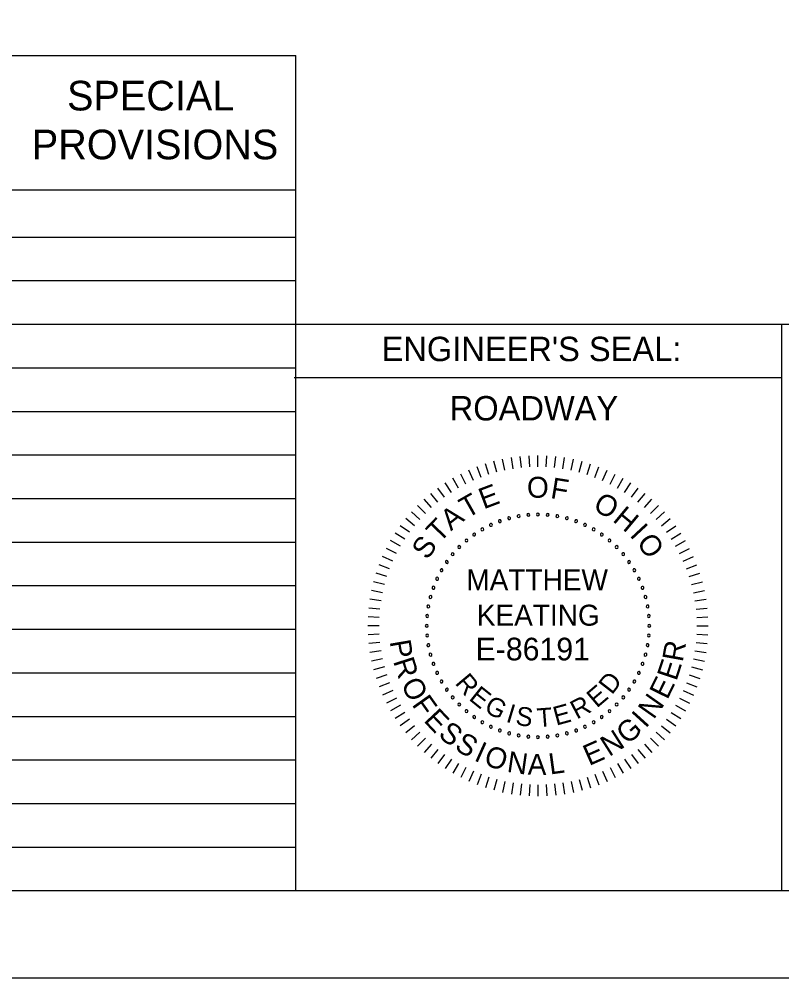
# Model space of a CAD drawing. Extents: x -13.1 to 43.1, y 0 to 22.
# Drawn here: x 23.44 to 27.81, y 0 to 5.5 of the extents above; entities that cross this region are included whole.
import ezdxf

# ---------------------------------------------------------------- set-up
doc = ezdxf.new("R2010")
doc.units = 0
for name, color, linetype in [('SEAL', 7, 'Continuous'), ('SH_Border', 7, 'Continuous'), ('SH_Data', 7, 'Continuous'), ('SH_Text', 7, 'Continuous')]:
    doc.layers.add(name, color=color, linetype=linetype)

msp = doc.modelspace()

# ---------------------------------------------------------------- linework, layer by layer
at = {"layer": 'SEAL'}
for p, q in [((26.2251, 2.9121), (26.2117, 2.9754)), ((26.2721, 2.9208), (26.262, 2.9847)), ((26.3195, 2.927), (26.3127, 2.9914)), ((26.3671, 2.9308), (26.3637, 2.9954)), ((26.4148, 2.932), (26.4148, 2.9967)), ((26.4626, 2.9308), (26.466, 2.9954)), ((26.5102, 2.927), (26.517, 2.9914)), ((26.5576, 2.9208), (26.5677, 2.9847)), ((26.6045, 2.9121), (26.618, 2.9754)), ((26.0878, 2.8714), (26.0647, 2.9318)), ((26.1329, 2.8874), (26.1129, 2.9489)), ((26.1787, 2.9009), (26.1619, 2.9634)), ((26.651, 2.9009), (26.6677, 2.9634)), ((26.6968, 2.8874), (26.7168, 2.9489)), ((26.7418, 2.8714), (26.765, 2.9318)), ((25.9586, 2.8098), (25.9263, 2.8658)), ((26.0006, 2.8326), (25.9712, 2.8902)), ((26.0437, 2.8531), (26.0174, 2.9123)), ((26.786, 2.8531), (26.8123, 2.9123)), ((26.8291, 2.8326), (26.8584, 2.8902)), ((26.8711, 2.8098), (26.9034, 2.8658)), ((25.8785, 2.7578), (25.8405, 2.8101)), ((25.9179, 2.7848), (25.8826, 2.8391)), ((26.9118, 2.7848), (26.947, 2.8391)), ((26.9512, 2.7578), (26.9892, 2.8101)), ((25.8406, 2.7287), (25.7999, 2.779)), ((26.989, 2.7287), (27.0298, 2.779)), ((25.7696, 2.6648), (25.7239, 2.7105)), ((25.8043, 2.6977), (25.761, 2.7458)), ((27.0254, 2.6977), (27.0687, 2.7458)), ((27.06, 2.6648), (27.1058, 2.7105)), ((25.7368, 2.6301), (25.6887, 2.6734)), ((27.0929, 2.6301), (27.141, 2.6734)), ((25.6767, 2.5559), (25.6243, 2.5939)), ((25.7057, 2.5938), (25.6554, 2.6345)), ((27.1239, 2.5938), (27.1742, 2.6345)), ((27.153, 2.5559), (27.2054, 2.5939)), ((25.6496, 2.5165), (25.5953, 2.5518)), ((27.1801, 2.5165), (27.2343, 2.5518)), ((25.6246, 2.4758), (25.5686, 2.5082)), ((27.205, 2.4758), (27.2611, 2.5082)), ((25.6018, 2.4338), (25.5442, 2.4632)), ((27.2278, 2.4338), (27.2855, 2.4632)), ((25.563, 2.3466), (25.5026, 2.3698)), ((25.5813, 2.3907), (25.5222, 2.417)), ((27.2484, 2.3907), (27.3075, 2.417)), ((27.2667, 2.3466), (27.3271, 2.3698)), ((25.547, 2.3016), (25.4855, 2.3215)), ((27.2826, 2.3016), (27.3442, 2.3215)), ((25.5335, 2.2557), (25.471, 2.2725)), ((27.2962, 2.2557), (27.3587, 2.2725)), ((25.5223, 2.2093), (25.459, 2.2228)), ((27.3073, 2.2093), (27.3706, 2.2228)), ((25.5136, 2.1623), (25.4497, 2.1725)), ((27.316, 2.1623), (27.3799, 2.1725)), ((25.5074, 2.115), (25.443, 2.1217)), ((27.3223, 2.115), (27.3866, 2.1217)), ((25.5036, 2.0673), (25.439, 2.0707)), ((27.326, 2.0673), (27.3906, 2.0707)), ((25.5024, 2.0196), (25.4377, 2.0196)), ((27.3273, 2.0196), (27.392, 2.0196)), ((25.5036, 1.9718), (25.439, 1.9685)), ((27.326, 1.9718), (27.3906, 1.9685)), ((25.5074, 1.9242), (25.443, 1.9175)), ((25.5136, 1.8769), (25.4497, 1.8667)), ((27.316, 1.8769), (27.3799, 1.8667)), ((27.3223, 1.9242), (27.3866, 1.9175)), ((25.5223, 1.8299), (25.459, 1.8164)), ((27.3073, 1.8299), (27.3706, 1.8164)), ((25.5335, 1.7834), (25.471, 1.7667)), ((27.2962, 1.7834), (27.3587, 1.7667)), ((25.547, 1.7376), (25.4855, 1.7176)), ((27.2826, 1.7376), (27.3442, 1.7176)), ((25.563, 1.6926), (25.5026, 1.6694)), ((27.2667, 1.6926), (27.3271, 1.6694)), ((25.5813, 1.6485), (25.5222, 1.6222)), ((25.6018, 1.6054), (25.5442, 1.576)), ((27.2278, 1.6054), (27.2855, 1.576)), ((27.2484, 1.6485), (27.3075, 1.6222)), ((25.6246, 1.5634), (25.5686, 1.531)), ((27.205, 1.5634), (27.2611, 1.531)), ((25.6496, 1.5226), (25.5953, 1.4874)), ((27.1801, 1.5226), (27.2343, 1.4874)), ((25.6767, 1.4833), (25.6243, 1.4452)), ((25.7057, 1.4454), (25.6554, 1.4047)), ((27.1239, 1.4454), (27.1742, 1.4047)), ((27.153, 1.4833), (27.2054, 1.4452)), ((25.7368, 1.4091), (25.6887, 1.3658)), ((27.0929, 1.4091), (27.141, 1.3658)), ((25.7696, 1.3744), (25.7239, 1.3286)), ((25.8043, 1.3415), (25.761, 1.2934)), ((27.0254, 1.3415), (27.0687, 1.2934)), ((27.06, 1.3744), (27.1058, 1.3286)), ((25.8406, 1.3105), (25.7999, 1.2602)), ((25.8785, 1.2814), (25.8405, 1.2291)), ((26.9512, 1.2814), (26.9892, 1.2291)), ((26.989, 1.3105), (27.0298, 1.2602)), ((25.9179, 1.2544), (25.8826, 1.2001)), ((25.9586, 1.2294), (25.9263, 1.1734)), ((26.8711, 1.2294), (26.9034, 1.1734)), ((26.9118, 1.2544), (26.947, 1.2001)), ((26.0006, 1.2066), (25.9712, 1.1489)), ((26.0437, 1.186), (26.0174, 1.1269)), ((26.0878, 1.1678), (26.0647, 1.1073)), ((26.7418, 1.1678), (26.765, 1.1073)), ((26.786, 1.186), (26.8123, 1.1269)), ((26.8291, 1.2066), (26.8584, 1.1489)), ((26.1329, 1.1518), (26.1129, 1.0903)), ((26.1787, 1.1382), (26.1619, 1.0757)), ((26.2251, 1.1271), (26.2117, 1.0638)), ((26.2721, 1.1184), (26.262, 1.0545)), ((26.3195, 1.1122), (26.3127, 1.0478)), ((26.3671, 1.1084), (26.3637, 1.0438)), ((26.4148, 1.1072), (26.4148, 1.0424)), ((26.4626, 1.1084), (26.466, 1.0438)), ((26.5102, 1.1122), (26.517, 1.0478)), ((26.5576, 1.1184), (26.5677, 1.0545)), ((26.6045, 1.1271), (26.618, 1.0638)), ((26.651, 1.1382), (26.6677, 1.0757)), ((26.6968, 1.1518), (26.7168, 1.0903))]:
    msp.add_line(p, q, dxfattribs=at)
for centre, start, end in [((26.2495, 2.6367), 15, 195), ((26.3039, 2.6488), 10, 190), ((26.3039, 2.6488), 190, 10), ((26.3591, 2.6561), 5, 185), ((26.3591, 2.6561), 185, 5), ((26.4148, 2.6585), 0, 180), ((26.4148, 2.6585), 180, 0), ((26.4705, 2.6561), 355, 175), ((26.4705, 2.6561), 175, 355), ((26.5258, 2.6488), 170, 350), ((26.5258, 2.6488), 350, 170), ((26.5802, 2.6367), 345, 165), ((26.1448, 2.5986), 25, 205), ((26.1448, 2.5986), 205, 25), ((26.1963, 2.62), 20, 200), ((26.1963, 2.62), 200, 20), ((26.2495, 2.6367), 195, 15), ((26.5802, 2.6367), 165, 345), ((26.6333, 2.62), 160, 340), ((26.6333, 2.62), 340, 160), ((26.6848, 2.5986), 155, 335), ((26.6848, 2.5986), 335, 155), ((26.0484, 2.543), 35, 215), ((26.0484, 2.543), 215, 35), ((26.0954, 2.5729), 30, 210), ((26.0954, 2.5729), 210, 30), ((26.7343, 2.5729), 150, 330), ((26.7343, 2.5729), 330, 150), ((26.7813, 2.543), 145, 325), ((26.7813, 2.543), 325, 145), ((25.9631, 2.4714), 45, 225), ((25.9631, 2.4714), 225, 45), ((26.0042, 2.509), 40, 220), ((26.0042, 2.509), 220, 40), ((26.8255, 2.509), 140, 320), ((26.8255, 2.509), 320, 140), ((26.8666, 2.4714), 135, 315), ((26.8666, 2.4714), 315, 135), ((25.9254, 2.4303), 50, 230), ((25.9254, 2.4303), 230, 50), ((26.9043, 2.4303), 130, 310), ((26.9043, 2.4303), 310, 130), ((25.8915, 2.3861), 55, 235), ((25.8915, 2.3861), 235, 55), ((26.9382, 2.3861), 125, 305), ((26.9382, 2.3861), 305, 125), ((25.8615, 2.339), 60, 240), ((25.8615, 2.339), 240, 60), ((26.9681, 2.339), 120, 300), ((26.9681, 2.339), 300, 120), ((25.8358, 2.2896), 65, 245), ((25.8358, 2.2896), 245, 65), ((26.9939, 2.2896), 115, 295), ((26.9939, 2.2896), 295, 115), ((25.8145, 2.2381), 70, 250), ((25.8145, 2.2381), 250, 70), ((27.0152, 2.2381), 110, 290), ((27.0152, 2.2381), 290, 110), ((25.7977, 2.185), 75, 255), ((25.7977, 2.185), 255, 75), ((27.032, 2.185), 105, 285), ((27.032, 2.185), 285, 105), ((25.7856, 2.1305), 80, 260), ((25.7856, 2.1305), 260, 80), ((27.044, 2.1305), 100, 280), ((27.044, 2.1305), 280, 100), ((25.7784, 2.0753), 85, 265), ((25.7784, 2.0753), 265, 85), ((27.0513, 2.0753), 95, 275), ((27.0513, 2.0753), 275, 95), ((25.7759, 2.0196), 90, 270), ((25.7759, 2.0196), 270, 90), ((27.0537, 2.0196), 90, 270), ((27.0537, 2.0196), 270, 90), ((25.7784, 1.9639), 95, 275), ((25.7784, 1.9639), 275, 95), ((27.0513, 1.9639), 85, 265), ((27.0513, 1.9639), 265, 85), ((25.7856, 1.9086), 100, 280), ((25.7856, 1.9086), 280, 100), ((27.044, 1.9086), 80, 260), ((27.044, 1.9086), 260, 80), ((25.7977, 1.8542), 105, 285), ((25.7977, 1.8542), 285, 105), ((27.032, 1.8542), 75, 255), ((27.032, 1.8542), 255, 75), ((25.8145, 1.8011), 110, 290), ((25.8145, 1.8011), 290, 110), ((27.0152, 1.8011), 70, 250), ((27.0152, 1.8011), 250, 70), ((25.8358, 1.7496), 115, 295), ((25.8358, 1.7496), 295, 115), ((25.8615, 1.7001), 120, 300), ((25.8615, 1.7001), 300, 120), ((26.9681, 1.7001), 60, 240), ((26.9681, 1.7001), 240, 60), ((26.9939, 1.7496), 65, 245), ((26.9939, 1.7496), 245, 65), ((25.8915, 1.6531), 125, 305), ((25.8915, 1.6531), 305, 125), ((26.9382, 1.6531), 55, 235), ((26.9382, 1.6531), 235, 55), ((25.9254, 1.6089), 130, 310), ((25.9254, 1.6089), 310, 130), ((26.9043, 1.6089), 50, 230), ((26.9043, 1.6089), 230, 50), ((25.9631, 1.5678), 135, 315), ((25.9631, 1.5678), 315, 135), ((26.8666, 1.5678), 45, 225), ((26.8666, 1.5678), 225, 45), ((26.0042, 1.5302), 140, 320), ((26.0042, 1.5302), 320, 140), ((26.0484, 1.4962), 145, 325), ((26.0484, 1.4962), 325, 145), ((26.7813, 1.4962), 35, 215), ((26.7813, 1.4962), 215, 35), ((26.8255, 1.5302), 40, 220), ((26.8255, 1.5302), 220, 40), ((26.0954, 1.4663), 150, 330), ((26.0954, 1.4663), 330, 150), ((26.1448, 1.4405), 155, 335), ((26.1448, 1.4405), 335, 155), ((26.6848, 1.4405), 25, 205), ((26.6848, 1.4405), 205, 25), ((26.7343, 1.4663), 30, 210), ((26.7343, 1.4663), 210, 30), ((26.1963, 1.4192), 160, 340), ((26.1963, 1.4192), 340, 160), ((26.2495, 1.4025), 165, 345), ((26.2495, 1.4025), 345, 165), ((26.3039, 1.3904), 170, 350), ((26.3039, 1.3904), 350, 170), ((26.3591, 1.3831), 355, 175), ((26.3591, 1.3831), 175, 355), ((26.4148, 1.3807), 0, 180), ((26.4148, 1.3807), 180, 0), ((26.4705, 1.3831), 5, 185), ((26.4705, 1.3831), 185, 5), ((26.5258, 1.3904), 10, 190), ((26.5258, 1.3904), 190, 10), ((26.5802, 1.4025), 15, 195), ((26.5802, 1.4025), 195, 15), ((26.6333, 1.4192), 20, 200), ((26.6333, 1.4192), 200, 20)]:
    msp.add_arc(centre, 0.00826, start, end, dxfattribs=at)
at = {"layer": 'SH_Border'}
msp.add_lwpolyline([(1.5, 21.5), (33.5, 21.5), (33.5, 0.5), (1.5, 0.5)], close=True, dxfattribs=at)
at = {"layer": 'SH_Data'}
for p, q in [((11.25, 5.2917), (25.0246, 5.2917)), ((25.0246, 0.5), (25.0246, 5.2917)), ((11.25, 4.5209), (25.0246, 4.5209)), ((21.25, 4.25), (25.0246, 4.25)), ((11.25, 4), (25.0246, 4)), ((11.25, 3.75), (25.0246, 3.75)), ((25.0148, 3.75), (30.6148, 3.75)), ((27.8148, 0.5), (27.8148, 3.75)), ((11.25, 3.5), (25.0246, 3.5)), ((25.0148, 3.4444), (27.8148, 3.4444)), ((11.25, 3.25), (25.0246, 3.25)), ((11.25, 3), (25.0246, 3)), ((11.25, 2.75), (25.0246, 2.75)), ((11.25, 2.5), (25.0246, 2.5)), ((11.25, 2.25), (25.0246, 2.25)), ((11.25, 2), (25.0246, 2)), ((11.25, 1.75), (25.0246, 1.75)), ((11.25, 1.5), (25.0246, 1.5)), ((11.25, 1.25), (25.0246, 1.25)), ((11.25, 1), (25.0246, 1)), ((11.25, 0.75), (25.0246, 0.75))]:
    msp.add_line(p, q, dxfattribs=at)
msp.add_lwpolyline([(0, 0), (34, 0), (34, 22), (0, 22)], close=True, dxfattribs=at)

# ---------------------------------------------------------------- texts
at = {"layer": 'SEAL'}
for s, height, rotation, p in [('O', 0.1203, 359.8493, (26.3514, 2.7544)), ('F', 0.1203, 350.7398, (26.4824, 2.7529)), ('E', 0.1203, 20.6845, (26.1029, 2.6871)), ('T', 0.1203, 29.5936, (26.0074, 2.6331)), ('O', 0.1203, 330.1051, (26.7243, 2.6891)), ('H', 0.1203, 320.1903, (26.8386, 2.6228)), ('T', 0.1203, 46.1424, (25.8495, 2.4916)), ('A', 0.1203, 38.3407, (25.9152, 2.561)), ('I', 0.1203, 312.9395, (26.9368, 2.5371)), ('S', 0.1203, 55.1599, (25.7799, 2.3933)), ('O', 0.1203, 305.2495, (26.9771, 2.4969)), ('P', 0.1203, 279.7454, (25.5628, 1.9301)), ('R', 0.1203, 79.7806, (27.2454, 1.8082)), ('R', 0.1203, 287.7472, (25.5821, 1.8168)), ('E', 0.1203, 71.7788, (27.2094, 1.6991)), ('O', 0.1203, 297.2934, (25.6251, 1.6856)), ('R', 0.1082, 309.8787, (25.9343, 1.6893)), ('D', 0.1082, 52.0798, (26.8392, 1.6198)), ('E', 0.1203, 63.7771, (27.157, 1.5916)), ('E', 0.1082, 321.3329, (26.0128, 1.5978)), ('E', 0.1082, 40.3546, (26.7523, 1.5446)), ('F', 0.1203, 305.2951, (25.6874, 1.5675)), ('G', 0.1082, 333.1405, (26.1001, 1.5283)), ('R', 0.1082, 27.8019, (26.6373, 1.4806)), ('N', 0.1203, 54.8716, (27.0791, 1.478)), ('E', 0.1203, 313.2969, (25.7542, 1.4741)), ('I', 0.1082, 343.0856, (26.2258, 1.4703)), ('S', 0.1082, 351.7916, (26.282, 1.4522)), ('T', 0.1082, 4.3443, (26.4128, 1.4372)), ('E', 0.1082, 15.2492, (26.5189, 1.4463)), ('I', 0.1203, 47.7736, (27.0322, 1.4278)), ('S', 0.1203, 321.2986, (25.8366, 1.3874)), ('G', 0.1203, 41.2489, (26.9294, 1.3337)), ('S', 0.1203, 329.3004, (25.9302, 1.3131)), ('N', 0.1203, 32.5477, (26.8236, 1.2663)), ('I', 0.1203, 335.7577, (26.0425, 1.2496)), ('O', 0.1203, 342.7173, (26.0985, 1.2227)), ('E', 0.1203, 23.7683, (26.7081, 1.2146)), ('N', 0.1203, 351.7612, (26.2323, 1.1822)), ('A', 0.1203, 359.763, (26.3553, 1.1649)), ('L', 0.1203, 7.7648, (26.484, 1.1662))]:
    msp.add_text(s, height=height, rotation=rotation, dxfattribs=at).set_placement(p)
for s, height, p in [('MATTHEW ', 0.12026, (26.0035, 2.2229)), ('KEATING', 0.12026, (26.0636, 2.0204)), ('E-86191', 0.12989, (26.0566, 1.8213))]:
    msp.add_text(s, height=height, dxfattribs=at).set_placement(p)
at = {"layer": 'SH_Text'}
for s, height, p in [('SPECIAL', 0.17, (23.711, 4.9763)), ('PROVISIONS', 0.17, (23.5089, 4.6963)), ("ENGINEER'S SEAL:", 0.14, (25.5168, 3.538)), ('ROADWAY', 0.14, (25.9081, 3.1978))]:
    msp.add_text(s, height=height, dxfattribs=at).set_placement(p)

doc.saveas('drawing.dxf')
